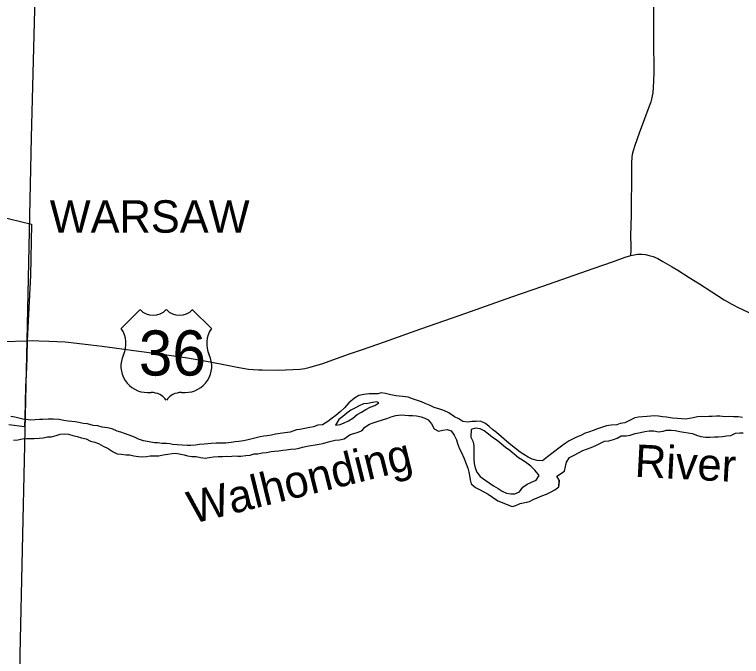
# Model space of a CAD drawing. Extents: x -6.3 to 34, y 0 to 22.
# Drawn here: x 1.87 to 3.325, y 14.392 to 15.677 of the extents above; entities that cross this region are included whole.
import ezdxf

# ---------------------------------------------------------------- set-up
doc = ezdxf.new("R2010")
doc.units = 0
for name, color, linetype in [('GM_X_Corporation', 7, 'Continuous'), ('GM_X_Corporation_Text', 7, 'Continuous'), ('GM_X_Major_River', 7, 'Continuous'), ('GM_X_Major_River_Text', 7, 'Continuous'), ('GM_X_Minor_River', 7, 'Continuous'), ('GM_X_State_Route', 7, 'Continuous'), ('GM_X_Township', 7, 'Continuous'), ('GM_X_US_Location', 7, 'Continuous'), ('GM_X_US_Route', 7, 'Continuous'), ('GM_X_US_Shield', 7, 'Continuous')]:
    doc.layers.add(name, color=color, linetype=linetype)

msp = doc.modelspace()

# ---------------------------------------------------------------- linework, layer by layer
at = {"layer": 'GM_X_Corporation'}
msp.add_lwpolyline([(1.8145, 15.2784), (1.9034, 15.2574), (1.9013, 15.1545), (1.8977, 15.0767), (1.8952, 15.0246), (1.8941, 14.9911), (1.8934, 14.9708), (1.892, 14.9445), (1.8917, 14.9318), (1.8902, 14.8705), (1.8897, 14.8517), (1.8585, 14.8556)], dxfattribs=at)
at = {"layer": 'GM_X_Major_River'}
for p, q in [((2.9596, 14.7315), (2.9598, 14.7454)), ((2.8371, 14.704), (2.8657, 14.6922))]:
    msp.add_line(p, q, dxfattribs=at)
for points in [[(3.0547, 14.8537), (3.0467, 14.8509), (3.0371, 14.8475), (3.028, 14.8443), (3.0208, 14.8417), (3.0122, 14.8391), (3.0032, 14.8347), (2.9944, 14.8313), (2.9869, 14.8274), (2.9801, 14.8235), (2.9721, 14.8185), (2.9646, 14.8128), (2.9455, 14.7987), (2.9364, 14.7917), (2.9266, 14.7841), (2.9162, 14.7846), (2.9058, 14.7872), (2.8978, 14.7911), (2.8892, 14.7963), (2.8822, 14.8009), (2.8729, 14.8084), (2.863, 14.8157), (2.8552, 14.8227), (2.8446, 14.832), (2.8345, 14.8406), (2.8264, 14.8465), (2.8197, 14.8522), (2.8124, 14.8587), (2.8023, 14.8631), (2.794, 14.8628), (2.7852, 14.8623), (2.7774, 14.861), (2.7673, 14.8625), (2.7593, 14.8675), (2.7507, 14.8716), (2.7388, 14.8801), (2.7292, 14.8843), (2.7212, 14.8874), (2.7095, 14.8907), (2.7015, 14.8944), (2.6919, 14.8988), (2.6841, 14.9016), (2.6745, 14.9052), (2.6667, 14.9078), (2.6576, 14.9109), (2.6473, 14.9122), (2.64, 14.9132), (2.6327, 14.9137), (2.6229, 14.916), (2.6123, 14.9184), (2.6037, 14.9196), (2.5967, 14.9178), (2.5884, 14.918), (2.5796, 14.9178), (2.569, 14.9167), (2.5589, 14.9144), (2.5501, 14.9089), (2.5392, 14.8998), (2.5304, 14.8899), (2.5219, 14.8821), (2.5129, 14.8745), (2.5056, 14.8691), (2.4971, 14.8625), (2.4865, 14.856), (2.4766, 14.855), (2.4681, 14.8516), (2.4611, 14.8508), (2.4543, 14.849), (2.4411, 14.8463), (2.4344, 14.8455), (2.4214, 14.8414), (2.4108, 14.8395), (2.4015, 14.8382), (2.3924, 14.8374), (2.3844, 14.8352), (2.3756, 14.8336), (2.3686, 14.833), (2.3611, 14.8319), (2.3531, 14.8298), (2.3451, 14.8275), (2.3371, 14.8256), (2.3283, 14.824), (2.3187, 14.8227), (2.3112, 14.8221), (2.3032, 14.8205), (2.2928, 14.8194), (2.2825, 14.8189), (2.2734, 14.8188), (2.2636, 14.8183), (2.2566, 14.8177), (2.2493, 14.8169), (2.24, 14.8166), (2.2317, 14.8153), (2.2229, 14.8147), (2.2154, 14.8147), (2.2051, 14.8149), (2.1955, 14.8159), (2.1862, 14.8167), (2.1804, 14.8177), (2.1742, 14.8182), (2.1654, 14.8184)], [(2.5988, 14.8996), (2.5949, 14.902), (2.5861, 14.9006), (2.5771, 14.8983), (2.5685, 14.8975), (2.5595, 14.8941), (2.5512, 14.8889), (2.5429, 14.885), (2.5349, 14.879), (2.5268, 14.8727), (2.5186, 14.8662), (2.5121, 14.855)], [(2.5121, 14.855), (2.5214, 14.8564), (2.5295, 14.8597), (2.5383, 14.8637), (2.5468, 14.8689), (2.5553, 14.8762), (2.5641, 14.8809), (2.5729, 14.8863), (2.5817, 14.891), (2.5913, 14.8942), (2.5988, 14.8996)], [(2.5419, 14.8366), (2.5489, 14.8382), (2.5577, 14.8411), (2.5658, 14.8442), (2.5709, 14.851), (2.5805, 14.857), (2.5878, 14.8599), (2.5958, 14.8622), (2.6064, 14.8661), (2.6168, 14.869), (2.6235, 14.8721), (2.6328, 14.8745), (2.6437, 14.8756), (2.651, 14.875), (2.659, 14.8748), (2.6665, 14.8746), (2.6745, 14.8735), (2.6839, 14.8715), (2.6911, 14.8689), (2.6979, 14.866), (2.7044, 14.8577), (2.7096, 14.8479), (2.7184, 14.8432), (2.7272, 14.8451), (2.7355, 14.8464), (2.7438, 14.8435), (2.75, 14.835), (2.7544, 14.8256), (2.7565, 14.8184), (2.7607, 14.8077), (2.7643, 14.8004), (2.769, 14.7901), (2.7735, 14.7779), (2.7771, 14.7688), (2.7789, 14.7612), (2.7802, 14.7542), (2.7821, 14.7459), (2.7839, 14.7379), (2.7927, 14.7304), (2.8005, 14.7267), (2.8176, 14.7169), (2.8264, 14.7109), (2.8371, 14.704)], [(3.3273, 14.8706), (3.3182, 14.8721), (3.3089, 14.8721), (3.3019, 14.8724), (3.2923, 14.8721), (3.2816, 14.8734), (3.2749, 14.8734), (3.2666, 14.8728), (3.2596, 14.8723), (3.2516, 14.8718), (3.2446, 14.8723), (3.2373, 14.8717), (3.228, 14.8699), (3.2213, 14.8683), (3.213, 14.8673), (3.2047, 14.868), (3.1969, 14.8688), (3.1871, 14.8693), (3.1749, 14.8711), (3.1666, 14.8716), (3.1586, 14.8729), (3.1513, 14.8739), (3.1433, 14.8731), (3.136, 14.8728), (3.1267, 14.872), (3.1187, 14.871), (3.1117, 14.8699), (3.1011, 14.8642), (3.0912, 14.8598), (3.0822, 14.8585), (3.0752, 14.8561), (3.0643, 14.855), (3.0547, 14.8537)], [(2.1654, 14.8184), (2.1558, 14.8197), (2.1501, 14.8199), (2.1393, 14.8217), (2.1281, 14.824), (2.1175, 14.827), (2.1097, 14.8309), (2.0991, 14.8353), (2.0895, 14.8386), (2.0823, 14.8412), (2.075, 14.8433), (2.0649, 14.8479), (2.0558, 14.8497), (2.0454, 14.8513), (2.0361, 14.8539), (2.027, 14.8544), (2.0155, 14.8576), (2.0072, 14.8586), (1.9981, 14.8604), (1.9911, 14.8616), (1.9846, 14.8626), (1.9771, 14.8634), (1.968, 14.8646), (1.9589, 14.8662), (1.9467, 14.8672), (1.9368, 14.8672), (1.9265, 14.8666), (1.9195, 14.8664), (1.9107, 14.8656), (1.9016, 14.865), (1.8928, 14.8663), (1.8861, 14.8671), (1.8783, 14.8691), (1.8702, 14.8709), (1.8619, 14.8727)], [(2.7839, 14.8467), (2.7832, 14.8311), (2.7876, 14.8215), (2.7889, 14.813), (2.7895, 14.8044), (2.7895, 14.7958), (2.7892, 14.787), (2.7898, 14.7782), (2.7919, 14.7696), (2.795, 14.7608), (2.802, 14.7522), (2.8113, 14.7457), (2.8197, 14.74), (2.8287, 14.7338), (2.8376, 14.7284), (2.8456, 14.7232), (2.8544, 14.7193), (2.863, 14.718), (2.8715, 14.718), (2.8803, 14.722), (2.8873, 14.7308), (2.8961, 14.7368), (2.9044, 14.741), (2.914, 14.7454), (2.9202, 14.7542)], [(2.9202, 14.7542), (2.9183, 14.7574), (2.9111, 14.7654), (2.903, 14.7729), (2.8952, 14.7794), (2.8869, 14.7853), (2.8789, 14.7897), (2.8698, 14.797), (2.8612, 14.8045), (2.8527, 14.8107), (2.8356, 14.8242), (2.8267, 14.8304), (2.8184, 14.8369), (2.8099, 14.8437), (2.8018, 14.8478), (2.7925, 14.8491), (2.7839, 14.8467)], [(2.9598, 14.7454), (2.9556, 14.753), (2.9709, 14.7632), (2.973, 14.7725), (2.9745, 14.7814), (2.9805, 14.7905), (2.99, 14.7952), (2.9988, 14.8001), (3.0076, 14.8043), (3.0146, 14.8074), (3.024, 14.8103), (3.0333, 14.8145), (3.0416, 14.8186), (3.0506, 14.8231), (3.0592, 14.8239), (3.0688, 14.8262), (3.0763, 14.8293), (3.0843, 14.8335), (3.0939, 14.8335), (3.1024, 14.8354), (3.1125, 14.8388), (3.1226, 14.8406), (3.1314, 14.8422), (3.1402, 14.8435), (3.1498, 14.8435), (3.1586, 14.8417), (3.168, 14.843), (3.1747, 14.8449), (3.184, 14.8454), (3.1926, 14.8444), (3.2014, 14.8423), (3.2099, 14.8413), (3.2185, 14.8397), (3.2273, 14.8385), (3.2353, 14.8354), (3.2439, 14.8328), (3.2527, 14.8312), (3.262, 14.8312), (3.2708, 14.832), (3.2781, 14.8321), (3.2869, 14.8323), (3.2952, 14.8336), (3.304, 14.8342), (3.3128, 14.8391), (3.3219, 14.8397), (3.3286, 14.8397)], [(1.8675, 14.8252), (1.8765, 14.8255), (1.8856, 14.8276), (1.8939, 14.8286), (1.9092, 14.8287), (1.919, 14.8292), (1.9271, 14.83), (1.9356, 14.8316), (1.9436, 14.8321), (1.9532, 14.8342), (1.9613, 14.8371), (1.9693, 14.8379), (1.9776, 14.8369), (1.9861, 14.8348), (1.995, 14.8322), (2.004, 14.8299), (2.0128, 14.8281), (2.0217, 14.8234), (2.0302, 14.8209), (2.038, 14.8183), (2.0468, 14.8131), (2.0572, 14.8082), (2.0668, 14.8017), (2.0753, 14.7978), (2.0834, 14.7968), (2.0932, 14.796), (2.1002, 14.7958), (2.1088, 14.7937), (2.1176, 14.7924), (2.1267, 14.7919), (2.1339, 14.7925), (2.1409, 14.7935), (2.1495, 14.7938), (2.1585, 14.7941), (2.1673, 14.7957), (2.1764, 14.7972), (2.1855, 14.7986), (2.1925, 14.7991), (2.1992, 14.7981), (2.2093, 14.796), (2.2161, 14.7939), (2.2244, 14.7927), (2.2332, 14.7927), (2.242, 14.7906), (2.2513, 14.7893), (2.2596, 14.7904), (2.2678, 14.7915), (2.2774, 14.7924), (2.286, 14.7927), (2.2932, 14.793), (2.301, 14.7927), (2.309, 14.7935), (2.3168, 14.7933), (2.3228, 14.7934), (2.3324, 14.7944), (2.3412, 14.7952), (2.3495, 14.7976), (2.3568, 14.7976), (2.3656, 14.7997), (2.3739, 14.8007), (2.3834, 14.8023), (2.3904, 14.8031), (2.3985, 14.8039), (2.4065, 14.805), (2.4137, 14.8055), (2.4228, 14.8073), (2.4327, 14.8081), (2.4394, 14.8089), (2.4461, 14.811), (2.4554, 14.8128), (2.463, 14.8142), (2.4718, 14.8155), (2.4793, 14.8173), (2.4868, 14.8186), (2.4935, 14.8207), (2.5034, 14.8231), (2.5114, 14.8249), (2.5202, 14.8257), (2.5298, 14.8278), (2.5419, 14.8366)], [(2.8657, 14.6922), (2.8736, 14.6947), (2.8822, 14.6981), (2.8912, 14.7004), (2.9003, 14.7025), (2.9081, 14.7064), (2.9158, 14.7098), (2.9252, 14.7137), (2.9345, 14.7169), (2.9428, 14.7213), (2.9513, 14.726), (2.9596, 14.7315)]]:
    msp.add_lwpolyline(points, dxfattribs=at)
at = {"layer": 'GM_X_Minor_River'}
msp.add_line((2.9598, 14.745), (2.9596, 14.7343), dxfattribs=at)
at = {"layer": 'GM_X_State_Route'}
msp.add_line((2.3578, 14.9657), (2.3652, 14.9657), dxfattribs=at)
for points in [[(3.1439, 15.5023), (3.1456, 15.5076), (3.147, 15.5139), (3.1482, 15.5203), (3.1492, 15.5315), (3.1498, 15.5437), (3.1503, 15.5616), (3.1495, 15.6255), (3.1494, 15.6519), (3.1498, 15.7411)], [(3.1036, 15.1948), (3.1039, 15.2062), (3.1038, 15.2411), (3.1041, 15.2475), (3.1049, 15.2826), (3.1051, 15.3017), (3.1053, 15.3393), (3.1055, 15.3805), (3.1059, 15.3905), (3.1071, 15.3974), (3.1086, 15.4047), (3.1122, 15.4155), (3.1209, 15.4401), (3.1422, 15.4971), (3.1439, 15.5023)], [(2.7615, 15.0754), (2.8655, 15.1117), (2.9271, 15.1335), (3.0282, 15.1689), (3.0685, 15.1827), (3.0919, 15.1911), (3.1036, 15.1948)], [(2.3652, 14.9657), (2.3977, 14.9654), (2.4414, 14.9673), (2.4508, 14.9684), (2.4617, 14.9709), (2.4867, 14.9788), (2.5066, 14.9859), (2.5403, 14.9976), (2.566, 15.0067), (2.6102, 15.0221), (2.6832, 15.0476), (2.7465, 15.0701), (2.7615, 15.0754)], [(1.8145, 15.0216), (1.8152, 15.0216), (1.8478, 15.0223), (1.8947, 15.024), (1.9062, 15.0244), (1.9185, 15.024)], [(1.9185, 15.024), (1.9392, 15.0233), (1.9712, 15.022), (1.9944, 15.0195), (2.0222, 15.0158), (2.0454, 15.0131), (2.0698, 15.0097)], [(2.0698, 15.0097), (2.1087, 15.0047), (2.1696, 14.9966), (2.2158, 14.9897), (2.2615, 14.9817), (2.2923, 14.9757), (2.3156, 14.9711), (2.338, 14.9673), (2.3472, 14.9663), (2.3578, 14.9657)]]:
    msp.add_lwpolyline(points, dxfattribs=at)
at = {"layer": 'GM_X_Township'}
msp.add_lwpolyline([(1.879, 14.2362), (1.8808, 14.3961), (1.8946, 15.0244), (1.9035, 15.4307), (1.9141, 15.8408), (1.9205, 16.0883), (1.9222, 16.1824), (1.9224, 16.1926), (1.9324, 16.7453), (1.9397, 17.1416)], dxfattribs=at)
at = {"layer": 'GM_X_US_Route'}
msp.add_line((2.3578, 14.9657), (2.3652, 14.9657), dxfattribs=at)
for points in [[(2.7615, 15.0754), (2.8655, 15.1117), (2.9271, 15.1335), (3.0282, 15.1689), (3.0685, 15.1827), (3.0919, 15.1911), (3.1036, 15.1948)], [(3.1036, 15.1948), (3.1171, 15.197), (3.1253, 15.1973), (3.1331, 15.1965), (3.1403, 15.1948), (3.1485, 15.1924), (3.1573, 15.1887), (3.1678, 15.1829), (3.1865, 15.1718), (3.1974, 15.165), (3.22, 15.1508), (3.2407, 15.1376), (3.2656, 15.1216), (3.2904, 15.1061), (3.3057, 15.0971), (3.3182, 15.0905), (3.4556, 15.0265), (3.5227, 14.9956), (3.5663, 14.9755)], [(2.3652, 14.9657), (2.3977, 14.9654), (2.4414, 14.9673), (2.4508, 14.9684), (2.4617, 14.9709), (2.4867, 14.9788), (2.5066, 14.9859), (2.5403, 14.9976), (2.566, 15.0067), (2.6102, 15.0221), (2.6832, 15.0476), (2.7465, 15.0701), (2.7615, 15.0754)], [(1.8145, 15.0216), (1.8152, 15.0216), (1.8478, 15.0223), (1.8947, 15.024), (1.9062, 15.0244), (1.9185, 15.024)], [(1.9185, 15.024), (1.9392, 15.0233), (1.9712, 15.022), (1.9944, 15.0195), (2.0222, 15.0158), (2.0454, 15.0131), (2.0698, 15.0097)], [(2.0698, 15.0097), (2.1087, 15.0047), (2.1696, 14.9966), (2.2158, 14.9897), (2.2615, 14.9817), (2.2923, 14.9757), (2.3156, 14.9711), (2.338, 14.9673), (2.3472, 14.9663), (2.3578, 14.9657)]]:
    msp.add_lwpolyline(points, dxfattribs=at)
at = {"layer": 'GM_X_US_Shield'}
for p, q in [((2.1208, 15.0862), (2.0832, 15.0485)), ((2.2639, 15.0485), (2.2262, 15.0862)), ((2.1359, 14.9205), (2.1434, 14.9205)), ((2.2037, 14.9205), (2.2112, 14.9205))]:
    msp.add_line(p, q, dxfattribs=at)
for centre, radius, start, end in [((2.1472, 15.1131), 0.0376, 225.573, 314.427), ((2.1999, 15.1131), 0.0376, 225.573, 314.427), ((2.04, 15.0183), 0.0527, 334.5471, 35.0009), ((2.3071, 15.0183), 0.0527, 144.9991, 205.4529), ((2.1353, 14.9733), 0.0527, 154.8319, 270.6383), ((2.2118, 14.9733), 0.0527, 269.3617, 25.1681), ((2.1434, 14.8829), 0.0376, 36.8699, 90), ((2.2037, 14.8829), 0.0376, 90, 143.1301)]:
    msp.add_arc(centre, radius, start, end, dxfattribs=at)

# ---------------------------------------------------------------- texts
at = {"layer": 'GM_X_Corporation_Text'}
msp.add_text('WARSAW', height=0.0649, rotation=0, dxfattribs=at).set_placement((1.9401, 15.2402))
at = {"layer": 'GM_X_Major_River_Text'}
for s, rotation, p in [('River', 356.9856, (3.1103, 14.7521)), ('Walhonding', 13.9879, (2.2254, 14.6573))]:
    msp.add_text(s, height=0.0649, rotation=rotation, dxfattribs=at).set_placement(p)
at = {"layer": 'GM_X_US_Location'}
for s in ['0', '/']:
    msp.add_text(s, height=0.00013, dxfattribs=at).set_placement((2.1735, 14.9989))
msp.add_text('36', height=0.00013, rotation=0, dxfattribs=at).set_placement((2.1467, 14.972))
at = {"layer": 'GM_X_US_Shield'}
msp.add_text('36', height=0.09035, dxfattribs=at).set_placement((2.1184, 14.9544))

doc.saveas('drawing.dxf')
